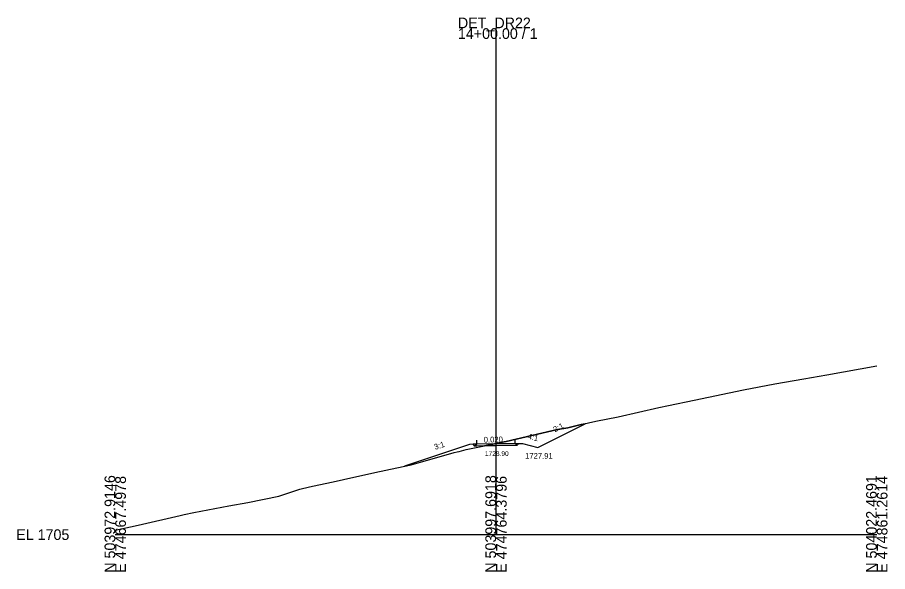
# Model space of a CAD drawing. Extents: x -26 to 1203, y -10 to 9633.
# Drawn here: x 974.3 to 1202.8, y -9.7 to 135.7 of the extents above; entities that cross this region are included whole.
import ezdxf

# ---------------------------------------------------------------- set-up
doc = ezdxf.new("R2010")
doc.units = 0
for name, color, linetype in [('Exist Cross Section Cell', 7, 'Continuous'), ('Exist XS Center Line Elevation Label', 7, 'Continuous'), ('Exist XS Ground Line', 7, 'Continuous'), ('Prop XS Ditch Slope Text', 7, 'Continuous'), ('Prop XS Ditch Standard Text', 7, 'Continuous'), ('Prop XS Earthwork Shape', 7, 'Continuous'), ('Prop XS EOT Tick Mark', 7, 'Continuous'), ('Prop XS Finish Grade', 7, 'Continuous'), ('Prop XS Finish Grade Earthwork', 7, 'Continuous'), ('Prop XS Finish Grade Pavement', 7, 'Continuous'), ('Prop XS Pvmt Edge Slope', 7, 'Continuous'), ('Prop XS SE Text', 7, 'Continuous'), ('Prop XS Shoulder Borrow Shape', 7, 'Continuous'), ('Prop XS Side Slope Text', 7, 'Continuous'), ('Prop XS Subgrade Earthwork', 7, 'Continuous')]:
    doc.layers.add(name, color=color, linetype=linetype)

msp = doc.modelspace()

# ---------------------------------------------------------------- linework, layer by layer
at = {"layer": 'Exist Cross Section Cell'}
for p, q in [((1100, 0), (1100, 132.88)), ((1000, 0), (1100, 0)), ((1100, 0), (1200, 0))]:
    msp.add_line(p, q, dxfattribs=at)
at = {"layer": 'Exist XS Ground Line'}
msp.add_lwpolyline([(1000, 1.16), (1006.01, 2.48), (1017.02, 5.05), (1018.07, 5.29), (1020.62, 5.8), (1029.81, 7.57), (1034.86, 8.42), (1042.95, 10.12), (1048.51, 11.97), (1049.18, 12.13), (1051.79, 12.74), (1057.26, 13.9), (1059.92, 14.48), (1068.21, 16.31), (1073.96, 17.51), (1077.69, 18.34), (1089, 21.53), (1089.81, 21.73), (1090.29, 21.84), (1092.16, 22.3), (1100, 23.9), (1101.18, 24.15), (1102.69, 24.4), (1116.19, 27.63), (1118.86, 28.01), (1122.37, 28.87), (1126.24, 29.76), (1132.1, 30.95), (1142.79, 33.32), (1145.27, 33.88), (1152.02, 35.32), (1164.98, 38), (1173.21, 39.54), (1180.8, 40.9), (1186.87, 41.96), (1200, 44.29)], dxfattribs=at)
at = {"layer": 'Prop XS Earthwork Shape'}
for points in [[(1107, 23.91), (1111, 22.91), (1123.38, 29.11), (1122.37, 28.87), (1118.86, 28.01), (1116.19, 27.63), (1102.69, 24.4), (1101.18, 24.15), (1100, 23.9), (1097.02, 23.29), (1100, 23.35), (1105, 23.45), (1105.53, 23.46), (1106.02, 23.95)], [(1094.45, 23.24), (1093.98, 23.71), (1093, 23.63), (1076, 17.97), (1077.69, 18.34), (1089, 21.53), (1089.81, 21.73), (1090.29, 21.84), (1092.16, 22.3), (1097.02, 23.29), (1095, 23.25)]]:
    msp.add_lwpolyline(points, close=True, dxfattribs=at)
at = {"layer": 'Prop XS EOT Tick Mark'}
for p, q in [((1095, 23.79), (1095, 24.79)), ((1105, 23.99), (1105, 24.99))]:
    msp.add_line(p, q, dxfattribs=at)
at = {"layer": 'Prop XS Finish Grade'}
for p, q in [((1095, 23.79), (1093.98, 23.71)), ((1105, 23.99), (1106.02, 23.95))]:
    msp.add_line(p, q, dxfattribs=at)
at = {"layer": 'Prop XS Finish Grade Earthwork'}
for p, q in [((1111, 22.91), (1123.38, 29.11)), ((1093, 23.63), (1076, 17.97)), ((1093.98, 23.71), (1093, 23.63)), ((1106.02, 23.95), (1107, 23.91)), ((1107, 23.91), (1111, 22.91))]:
    msp.add_line(p, q, dxfattribs=at)
at = {"layer": 'Prop XS Finish Grade Pavement'}
for p, q in [((1095, 23.79), (1100, 23.89)), ((1100, 23.89), (1105, 23.99))]:
    msp.add_line(p, q, dxfattribs=at)
at = {"layer": 'Prop XS Pvmt Edge Slope'}
for p, q in [((1095, 23.79), (1094.45, 23.24)), ((1105, 23.99), (1105.53, 23.46))]:
    msp.add_line(p, q, dxfattribs=at)
at = {"layer": 'Prop XS Shoulder Borrow Shape'}
for points in [[(1095, 23.79), (1093.98, 23.71), (1094.45, 23.24)], [(1105, 23.99), (1106.02, 23.95), (1105.53, 23.46)]]:
    msp.add_lwpolyline(points, close=True, dxfattribs=at)
at = {"layer": 'Prop XS Subgrade Earthwork'}
for p, q in [((1094.45, 23.24), (1093.98, 23.71)), ((1095, 23.25), (1094.45, 23.24)), ((1100, 23.35), (1095, 23.25)), ((1105, 23.45), (1100, 23.35)), ((1105, 23.45), (1105.53, 23.46)), ((1105.53, 23.46), (1106.02, 23.95))]:
    msp.add_line(p, q, dxfattribs=at)

# ---------------------------------------------------------------- texts
at = {"layer": 'Exist Cross Section Cell'}
for s, p in [('DET_DR22', (1090, 132.88)), ('14+00.00 / 1', (1090, 130.08)), ('EL 1705', (974, -1.4))]:
    msp.add_text(s, height=2.8, dxfattribs=at).set_placement(p)
for s, p in [('N 503972.9146', (1000, -10)), ('E 474667.4978', (1002.8, -10)), ('N 503997.6918', (1100, -10)), ('E 474764.3796', (1102.8, -10)), ('N 504022.4691', (1200, -10)), ('E 474861.2614', (1202.8, -10))]:
    msp.add_text(s, height=2.8, rotation=90, dxfattribs=at).set_placement(p)
at = {"layer": 'Exist XS Center Line Elevation Label'}
msp.add_text('1728.90', height=1.25, dxfattribs=at).set_placement((1097.09, 20.65))
at = {"layer": 'Prop XS Ditch Slope Text'}
msp.add_text('4:1', height=1.5, rotation=345.9638, dxfattribs=at).set_placement((1108.21, 25.16))
at = {"layer": 'Prop XS Ditch Standard Text'}
msp.add_text('1727.91', height=1.5, dxfattribs=at).set_placement((1107.64, 19.91))
at = {"layer": 'Prop XS SE Text'}
msp.add_text('0.020', height=1.5, rotation=1.1458, dxfattribs=at).set_placement((1096.8, 24.15))
at = {"layer": 'Prop XS Side Slope Text'}
for s, rotation, p in [('2:1', 26.5651, (1115.46, 26.82)), ('3:1', 18.4349, (1084.03, 22.22))]:
    msp.add_text(s, height=1.5, rotation=rotation, dxfattribs=at).set_placement(p)

doc.saveas('drawing.dxf')
